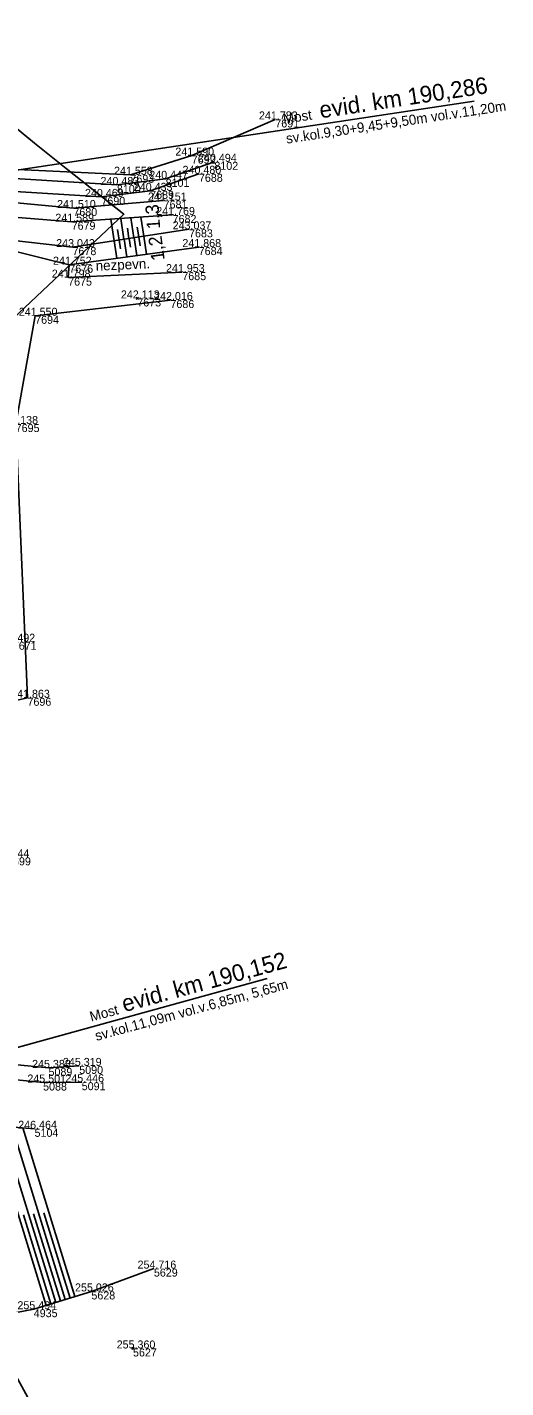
# Model space of a CAD drawing. Extents: x -809970 to -809480, y -1011362 to -1010672.
# Drawn here: x -809812.8 to -809741.1, y -1011032.7 to -1010828.7 of the extents above; entities that cross this region are included whole.
import ezdxf

# ---------------------------------------------------------------- set-up
doc = ezdxf.new("R2010")
doc.units = 0
for name, color, linetype in [('Vrstva 13', 7, 'Continuous'), ('Vrstva 17', 7, 'Continuous'), ('Vrstva 18', 7, 'Continuous'), ('Vrstva 48', 7, 'Continuous'), ('Vrstva 49', 7, 'Continuous'), ('Vrstva 50', 7, 'Continuous'), ('Vrstva 51', 7, 'Continuous'), ('Vrstva 53', 7, 'Continuous'), ('Vrstva 60', 7, 'Continuous'), ('Vrstva 61', 7, 'Continuous')]:
    doc.layers.add(name, color=color, linetype=linetype)

msp = doc.modelspace()

# ---------------------------------------------------------------- linework, layer by layer
at = {"layer": 'Vrstva 13'}
for points in [[(-809898.02, -1010866.97), (-809878.97, -1010859.3), (-809872.35, -1010857.62), (-809867.96, -1010856.6), (-809820.69, -1010849.74), (-809797.36, -1010850.83), (-809788.17, -1010847.96), (-809775.64, -1010842.54)], [(-809898.38, -1010868.53), (-809878.32, -1010860.12), (-809872.07, -1010858.41), (-809867.89, -1010857.64), (-809821.24, -1010851), (-809799.39, -1010852.36), (-809792.08, -1010851.44), (-809784.77, -1010848.89)], [(-809898.22, -1010870.02), (-809885.88, -1010864.68), (-809874.42, -1010861.27), (-809865.77, -1010859.37), (-809858.59, -1010858.13), (-809838.65, -1010854.72), (-809823.56, -1010852.79), (-809801.71, -1010854.15), (-809794.4, -1010853.24), (-809787.09, -1010850.69)], [(-809895.52, -1010870.31), (-809884.62, -1010865.27), (-809874.48, -1010862.4), (-809857.42, -1010859.36), (-809838.69, -1010855.97), (-809825.12, -1010854.03), (-809805.91, -1010855.82), (-809792.38, -1010854.69)]]:
    msp.add_lwpolyline(points, dxfattribs=at)
at = {"layer": 'Vrstva 17'}
msp.add_lwpolyline([(-809816.37, -1010956.51), (-809815.85, -1010953.16), (-809816.89, -1010937.94), (-809817.02, -1010930.19), (-809812.79, -1010929.24), (-809814.56, -1010888.2), (-809811.64, -1010871.97), (-809791.36, -1010869.61)], dxfattribs=at)
at = {"layer": 'Vrstva 18'}
for p, q in [((-809745.84, -1010839.81), (-809860.35, -1010857.06)), ((-809776.85, -1010971.33), (-809835.71, -1010987.56))]:
    msp.add_line(p, q, dxfattribs=at)
at = {"layer": 'Vrstva 48'}
for p, q in [((-809799.81, -1010860.73), (-809800.31, -1010857.48)), ((-809798.33, -1010860.5), (-809798.81, -1010857.38)), ((-809797.59, -1010860.39), (-809797.82, -1010858.86)), ((-809796.85, -1010860.28), (-809797.3, -1010857.28)), ((-809796.1, -1010860.16), (-809796.33, -1010858.69)), ((-809795.36, -1010860.05), (-809795.8, -1010857.18)), ((-809799.79, -1010860.73), (-809799.39, -1010863.35)), ((-809799.07, -1010860.62), (-809799.31, -1010859.02)), ((-809799.05, -1010860.61), (-809798.85, -1010861.93)), ((-809798.31, -1010860.5), (-809797.9, -1010863.14)), ((-809797.56, -1010860.39), (-809797.36, -1010861.71)), ((-809796.82, -1010860.27), (-809796.42, -1010862.94)), ((-809796.08, -1010860.16), (-809795.88, -1010861.5)), ((-809795.34, -1010860.05), (-809794.93, -1010862.74)), ((-809809.99, -1011020.33), (-809818.31, -1010993.32)), ((-809808.56, -1011019.89), (-809816.7, -1010993.45)), ((-809807.12, -1011019.45), (-809815.09, -1010993.59)), ((-809805.69, -1011019.01), (-809813.48, -1010993.72)), ((-809809.27, -1011020.11), (-809813.39, -1011006.75)), ((-809807.84, -1011019.67), (-809811.87, -1011006.59)), ((-809806.41, -1011019.23), (-809810.34, -1011006.44))]:
    msp.add_line(p, q, dxfattribs=at)
at = {"layer": 'Vrstva 49'}
for p, q in [((-809796.51, -1010869.19), (-809796.16, -1010869.54)), ((-809796.51, -1010869.54), (-809796.16, -1010869.19)), ((-809797.15, -1011026.62), (-809796.8, -1011026.97)), ((-809797.15, -1011026.97), (-809796.8, -1011026.62))]:
    msp.add_line(p, q, dxfattribs=at)
for points in [[(-809791.03, -1010856.86), (-809806.17, -1010857.87), (-809825.97, -1010856.27), (-809840.11, -1010858.34), (-809856.78, -1010861.08), (-809874.48, -1010862.4), (-809884.62, -1010865.27), (-809895.52, -1010870.31)], [(-809788.57, -1010859.01), (-809806.04, -1010861.68), (-809826.32, -1010859.41), (-809840.96, -1010860.18), (-809855.71, -1010862.54), (-809858.57, -1010861.92), (-809859.81, -1010861.34), (-809864.88, -1010862.16), (-809868.61, -1010862.71), (-809873.88, -1010863.22), (-809883.3, -1010866.23), (-809893.78, -1010870.48)], [(-809787.12, -1010861.67), (-809806.52, -1010864.32), (-809826.32, -1010859.41)], [(-809824.52, -1010995.16), (-809824.64, -1010994.76), (-809822.31, -1010993), (-809811.73, -1010993.86)], [(-809814.25, -1011034.46), (-809820.96, -1011021.87), (-809820.29, -1011021.55), (-809817.36, -1011021.94), (-809811.85, -1011020.91), (-809803.21, -1011018.24), (-809793.84, -1011014.82)]]:
    msp.add_lwpolyline(points, dxfattribs=at)
at = {"layer": 'Vrstva 50'}
for points in [[(-809898.38, -1010868.53), (-809878.32, -1010860.12), (-809872.07, -1010858.41), (-809867.89, -1010857.64), (-809821.24, -1010851), (-809799.39, -1010852.36), (-809792.08, -1010851.44), (-809784.77, -1010848.89)], [(-809898.22, -1010870.02), (-809885.88, -1010864.68), (-809874.42, -1010861.27), (-809865.77, -1010859.37), (-809858.59, -1010858.13), (-809838.65, -1010854.72), (-809823.56, -1010852.79), (-809801.71, -1010854.15), (-809794.4, -1010853.24), (-809787.09, -1010850.69)]]:
    msp.add_lwpolyline(points, dxfattribs=at)
at = {"layer": 'Vrstva 51'}
for points in [[(-809789.58, -1010865.43), (-809806.69, -1010866.25), (-809806.52, -1010864.32), (-809787.12, -1010861.67)], [(-809868.18, -1010980.13), (-809861.52, -1010984.44), (-809856.27, -1010987.12), (-809851.69, -1010988.36), (-809846.09, -1010987.91), (-809837.05, -1010985.07), (-809827.69, -1010983.65), (-809817.51, -1010983.98), (-809809.64, -1010984.73), (-809805.03, -1010984.43)], [(-809869.14, -1010983.26), (-809862.74, -1010986.47), (-809856.66, -1010989.93), (-809852.55, -1010991.52), (-809844.99, -1010990.28), (-809835.97, -1010987.57), (-809827.37, -1010986.17), (-809817.54, -1010986.23), (-809810.45, -1010986.92), (-809804.66, -1010986.87)]]:
    msp.add_lwpolyline(points, dxfattribs=at)
at = {"layer": 'Vrstva 53'}
msp.add_lwpolyline([(-809848.47, -1010824.63), (-809848.99, -1010834.52), (-809828.94, -1010831.94), (-809811.76, -1010846.11), (-809806.99, -1010849.89), (-809798.33, -1010856.76), (-809803.49, -1010861.61), (-809820.27, -1010877.38), (-809819.54, -1010907.65), (-809817.34, -1010954.54), (-809819.55, -1010971.19), (-809826.87, -1010981.55), (-809825.08, -1010988.69), (-809823.59, -1010994.66), (-809817.83, -1011024.91), (-809805.06, -1011048.21)], dxfattribs=at)
at = {"layer": 'Vrstva 60'}
for p, q in [((-809775.64, -1010842.54), (-809775.64, -1010842.54)), ((-809788.17, -1010847.96), (-809788.17, -1010847.96)), ((-809797.36, -1010850.83), (-809797.36, -1010850.83)), ((-809787.09, -1010850.69), (-809787.09, -1010850.69)), ((-809784.77, -1010848.89), (-809784.77, -1010848.89)), ((-809799.39, -1010852.36), (-809799.39, -1010852.36)), ((-809792.08, -1010851.44), (-809792.08, -1010851.44)), ((-809801.71, -1010854.15), (-809801.71, -1010854.15)), ((-809794.4, -1010853.24), (-809794.4, -1010853.24)), ((-809792.38, -1010854.69), (-809792.38, -1010854.69)), ((-809805.91, -1010855.82), (-809805.91, -1010855.82)), ((-809791.03, -1010856.86), (-809791.03, -1010856.86)), ((-809806.17, -1010857.87), (-809806.17, -1010857.87)), ((-809788.57, -1010859.01), (-809788.57, -1010859.01)), ((-809806.04, -1010861.68), (-809806.04, -1010861.68)), ((-809787.12, -1010861.67), (-809787.12, -1010861.67)), ((-809806.52, -1010864.32), (-809806.52, -1010864.32)), ((-809806.69, -1010866.25), (-809806.69, -1010866.25)), ((-809789.58, -1010865.43), (-809789.58, -1010865.43)), ((-809796.33, -1010869.37), (-809796.33, -1010869.37)), ((-809791.36, -1010869.61), (-809791.36, -1010869.61)), ((-809811.64, -1010871.97), (-809811.64, -1010871.97)), ((-809812.79, -1010929.24), (-809812.79, -1010929.24)), ((-809809.64, -1010984.73), (-809809.64, -1010984.73)), ((-809805.03, -1010984.43), (-809805.03, -1010984.43)), ((-809810.45, -1010986.92), (-809810.45, -1010986.92)), ((-809804.66, -1010986.87), (-809804.66, -1010986.87)), ((-809811.73, -1010993.86), (-809811.73, -1010993.86)), ((-809793.84, -1011014.82), (-809793.84, -1011014.82)), ((-809803.21, -1011018.24), (-809803.21, -1011018.24)), ((-809811.85, -1011020.91), (-809811.85, -1011020.91)), ((-809796.97, -1011026.79), (-809796.97, -1011026.79))]:
    msp.add_line(p, q, dxfattribs=at)

# ---------------------------------------------------------------- texts
at = {"layer": 'Vrstva 18'}
for s, height, rotation, p in [('evid. km 190,286', 2.5, 8.5615, (-809768.84, -1010842.38)), ('sv.kol.9,30+9,45+9,50m vol.v.11,20m', 1.5, 8.5615, (-809773.92, -1010846.17)), ('Most', 1.5, 8.5615, (-809774.37, -1010843.2)), ('evid. km 190,152', 2.5, 15.2369, (-809798.27, -1010976.38)), ('sv.kol.11,09m vol.v.6,85m, 5,65m', 1.5, 15.2369, (-809802.44, -1010980.69)), ('Most', 1.5, 15.2369, (-809803.23, -1010977.8))]:
    msp.add_text(s, height=height, rotation=rotation, dxfattribs=at).set_placement(p)
at = {"layer": 'Vrstva 48'}
for s, rotation, p in [('1,3', 93.8108, (-809792.89, -1010858.92)), ('1,2', 97.7627, (-809792.21, -1010863.57))]:
    msp.add_text(s, height=2, rotation=rotation, dxfattribs=at).set_placement(p)
at = {"layer": 'Vrstva 51'}
msp.add_text('nezpevn.', height=1.5, rotation=2.7179, dxfattribs=at).set_placement((-809802.53, -1010865.24))
at = {"layer": 'Vrstva 60'}
for s, p in [('7691', (-809775.64, -1010843.74)), ('7692', (-809788.17, -1010849.16)), ('7693', (-809797.36, -1010852.03)), ('7688', (-809787.09, -1010851.89)), ('8102', (-809784.77, -1010850.09)), ('8100', (-809799.39, -1010853.56)), ('8101', (-809792.08, -1010852.64)), ('7690', (-809801.71, -1010855.35)), ('7689', (-809794.4, -1010854.44)), ('7681', (-809792.38, -1010855.89)), ('7680', (-809805.91, -1010857.02)), ('7682', (-809791.03, -1010858.06)), ('7679', (-809806.17, -1010859.07)), ('7683', (-809788.57, -1010860.21)), ('7678', (-809806.04, -1010862.88)), ('7684', (-809787.12, -1010862.87)), ('7676', (-809806.52, -1010865.52)), ('7675', (-809806.69, -1010867.45)), ('7685', (-809789.58, -1010866.63)), ('7673', (-809796.33, -1010870.57)), ('7686', (-809791.36, -1010870.81)), ('7694', (-809811.64, -1010873.17)), ('7695', (-809814.56, -1010889.4)), ('7671', (-809814.99, -1010922.04)), ('7696', (-809812.79, -1010930.44)), ('7699', (-809815.85, -1010954.36)), ('5089', (-809809.64, -1010985.93)), ('5090', (-809805.03, -1010985.63)), ('5088', (-809810.45, -1010988.12)), ('5091', (-809804.66, -1010988.07)), ('5104', (-809811.73, -1010995.06)), ('5629', (-809793.84, -1011016.02)), ('5628', (-809803.21, -1011019.44)), ('4935', (-809811.85, -1011022.1)), ('5627', (-809796.97, -1011027.99))]:
    msp.add_text(s, height=1.2, dxfattribs=at).set_placement(p)
at = {"layer": 'Vrstva 61'}
for s, p in [('241.783', (-809778.09, -1010842.54)), ('241.590', (-809790.62, -1010847.96)), ('240.494', (-809787.22, -1010848.89)), ('241.558', (-809799.82, -1010850.83)), ('240.447', (-809794.53, -1010851.44)), ('240.480', (-809789.54, -1010850.69)), ('240.483', (-809801.84, -1010852.36)), ('240.433', (-809796.85, -1010853.24)), ('241.510', (-809808.36, -1010855.82)), ('240.469', (-809804.17, -1010854.15)), ('241.151', (-809794.73, -1010854.69)), ('241.589', (-809808.62, -1010857.87)), ('241.769', (-809793.49, -1010856.86)), ('243.037', (-809791.03, -1010859.01)), ('243.043', (-809808.49, -1010861.68)), ('241.868', (-809789.57, -1010861.67)), ('241.798', (-809809.14, -1010866.25)), ('241.752', (-809808.97, -1010864.32)), ('241.953', (-809792.03, -1010865.43)), ('242.113', (-809798.79, -1010869.37)), ('242.016', (-809793.81, -1010869.61)), ('241.550', (-809814.09, -1010871.97)), ('242.138', (-809817.01, -1010888.2)), ('241.492', (-809817.44, -1010920.84)), ('241.863', (-809815.24, -1010929.24)), ('243.344', (-809818.31, -1010953.16)), ('245.319', (-809807.48, -1010984.43)), ('245.388', (-809812.1, -1010984.73)), ('245.501', (-809812.81, -1010986.92)), ('245.446', (-809807.11, -1010986.87)), ('246.464', (-809814.18, -1010993.86)), ('254.716', (-809796.29, -1011014.82)), ('255.026', (-809805.66, -1011018.24)), ('255.494', (-809814.3, -1011020.91)), ('255.360', (-809799.42, -1011026.79))]:
    msp.add_text(s, height=1.2, dxfattribs=at).set_placement(p)

doc.saveas('drawing.dxf')
